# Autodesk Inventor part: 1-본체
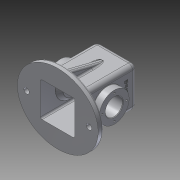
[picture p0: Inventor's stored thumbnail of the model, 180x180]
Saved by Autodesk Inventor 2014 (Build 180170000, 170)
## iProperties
Created: 2017-07
Part Number: 1-본체
Material: Aluminum 6061
Document SubType Name: Modeling
Designer: user
Density: 2.71 g/cm^3
Appearance: Aluminum - Flat
Mass: 892.712 g
Surface Area: 987.354 cm^2
Volume: 329.414 cm^3
Author: user
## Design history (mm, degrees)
sketch "Sketch1" dims "d4" = 65, "d6" = 75
  geometry: 2 further points; 1 other entity
  constraints: 1 coincident, 2 other
extrude "Extrusion1" new body sketch "Sketch1" distance "d7" = 10; taper "d8" = 0 deg
sketch "Sketch2"
  geometry: L1 (-37, -37)-(37, -37); L2 (37, -37)-(37, 37); L3 (37, 37)-(-37, 37); L4 (-37, 37)-(-37, -37); L5 (-37, -37)-(37, 37); L6 (37, -37)-(-37, 37); 1 further point
  constraints: 12 end point, 2 midpoint, 2 parallel, 1 horizontal, 1 perpendicular
  dimensions: "d9" = 74 distance of L3.end L2.end; "d10" = 74 distance of L2.end L1.end
extrude "Extrusion2" join sketch "Sketch2" distance "d11" = 100; taper "d12" = 0 deg
sketch "Sketch3"
  geometry: L1 (-32, 105)-(32, 105); L2 (-32, 105)-(-32, 0); L3 (32, 105)-(32, 0); L4 (-32, 0)-(32, 0); L5 (37, 110)-(-37, 110) reference; 1 further point
  constraints: 8 end point, 3 parallel, 1 perpendicular
  dimensions: "d16" = 5 horizontal distance of L1.end L5.start; "d17" = 110 distance between parallel lines of L4 L5; "d18" = 64 distance between parallel lines of L3 L2; "d19" = 5 distance from line of L5.start L3
extrude "Extrusion3" cut sketch "Sketch3" stored distance "d20" = 64; taper "d21" = 0 deg
sketch "Sketch4"
  geometry: C1 r 27.5 at (37, 45); 1 further point
  constraints: 1 centre point, 1 vertical alignment
  dimensions: "d30" = 55 diameter of C1; "d31" = 55 distance of C1.centre point (37, -10)
extrude "Extrusion4" join sketch "Sketch4" distance "d32" = 13; taper "d33" = 0 deg
sketch "Sketch5"
  geometry: C1 r 27.5 at (37, 45); 1 further point
  constraints: 1 centre point, 1 vertical alignment
  dimensions: "d35" = 55 diameter of C1; "d36" = 55 distance of C1.centre point (37, -10)
extrude "Extrusion5" join sketch "Sketch5" distance "d37" = 13; taper "d38" = 0 deg
sketch "Sketch6"
  geometry: C1 r 27.5 at (0, 0) reference; C2 r 16 at (0, 0); 1 further point
  constraints: 1 centre point, 1 coincident
  dimensions: "d39" = 32 diameter of C2
extrude "Extrusion6" cut sketch "Sketch6" stored distance "d40" = 13; taper "d41" = 0 deg
sketch "Sketch7"
  geometry: L1 (50, 82.5)-(32, 82.5); L2 (32, 82.5)-(25, 75.5); L3 (32, 82.5)-(41.899, 82.5); L4 (25, 75.5)-(25, 55); L5 (25, 55)-(50, 55); L6 (50, 82.5)-(50, 55); 1 further point
  constraints: 12 end point, 2 perpendicular, 1 equal length, 1 horizontal, 1 vertical
  dimensions: "d49" = 135 deg angle of L2 L3; "d50" = 7 horizontal distance of L1.end L2.end; "d51" = 55 vertical distance of point (0, 0) L4.end; "d52" = 90 deg angle of L6 L1; "d55" = 25 horizontal distance of L1.start L2.end
revolve "Revolution1" sketch "Sketch7" stored, may be unused: angle "d54" = 90 deg
sketch "Sketch8"
  geometry: L1 (-50, 82.5)-(-32, 82.5); L2 (-32, 82.5)-(-25, 75.5); L3 (-25, 75.5)-(-25, 55); L4 (-50, 55)-(-25, 55); L5 (-50, 82.5)-(-50, 55); 1 further point
  constraints: 10 end point, 3 perpendicular, 1 vertical
  dimensions: "d63" = 7 horizontal distance of L1.end L2.end; "d64" = 135 deg angle of L2 L1; "d65" = 55 vertical distance of point (0, 0) L3.end; "d66" = 25 distance between parallel lines of L5 L3
revolve "Revolution2" sketch "Sketch8" stored, may be unused: angle "d67" = 90 deg
sketch "Sketch9"
  geometry: C1 r 27.5 at (0, 0) reference; C2 r 16 at (0, 0); 1 further point
  constraints: 1 centre point, 1 coincident
  dimensions: "d68" = 32 diameter of C2
extrude "Extrusion7" cut sketch "Sketch9" stored distance "d69" = 13; taper "d70" = 0 deg
workplane "Work Plane1"
sketch "Sketch10"
  geometry: L1 (20, -20)-(-20, -20); L2 (-20, -20)-(-20, 20); L3 (-20, 20)-(20, 20); L4 (20, 20)-(20, -20); L5 (20, -20)-(-20, 20); L6 (-20, -20)-(20, 20); 1 further point
  constraints: 12 end point, 2 midpoint, 2 parallel, 1 horizontal, 1 perpendicular
  dimensions: "d72" = 40 distance of L2.end L3.end; "d73" = 40 distance of L1.end L2.end
extrude "Extrusion8" join sketch "Sketch10" stored distance "d74" = 13; taper "d75" = 0 deg
sketch "Sketch11"
  geometry: C1 r 14 at (0, 0); 1 further point
  constraints: 1 centre point, 1 coincident
  dimensions: "d76" = 28 diameter of C1
extrude "Extrusion9" cut sketch "Sketch11" distance "d77" = 4; taper "d78" = 0 deg
sketch "Sketch12"
  geometry: C1 r 10.5 at (0, 0); 1 further point
  constraints: 1 centre point, 1 coincident
  dimensions: "d79" = 21 diameter of C1
extrude "Extrusion10" cut sketch "Sketch12" distance "d80" = 50; taper "d81" = 0 deg
feature "FaceDraft1" dims angle "d82" = 5 deg
feature "FaceDraft2" dims angle "d154" = 5 deg
sketch "Sketch13"
  geometry: C1 r 27.5 at (0, 0) reference; 5 further points
  dimensions: "d84" = 59.42432 distance of point (0, -55) point (22.5, 0); "d85" = 77.5 distance of point (0, -55) point (0, 22.5); "d86" = 32.5 distance of point (0, -55) point (0, -22.5); "d87" = 59.42432 distance of point (0, -55) point (-22.5, 0); "d88" = 31.81981 distance of point (22.5, 0) point (0, 22.5); "d89" = 31.81981 distance of point (22.5, 0) point (0, -22.5); "d90" = 45 distance of point (22.5, 0) point (-22.5, 0); "d91" = 22.5 distance of C1.centre point (22.5, 0)
hole "Hole1" sketch "Sketch13" at (0, 22.5), (22.5, 0), (0, -22.5), (-22.5, 0) diameter "d92" = 3.242; stored, may be unused: countersink angle "d96" = 90 deg, drill point angle "d98" = 118 deg; dims "d93" = 8, "d94" = 4, "d95" = 2, "d97" = 10
sketch "Sketch14"
  geometry: C1 r 27.5 at (0, 0) reference; 5 further points
  dimensions: "d100" = 22.5 distance of C1.centre point (22.5, 0); "d101" = 59.42432 distance of point (0, -55) point (22.5, 0); "d102" = 22.5 distance of C1.centre point (0, 22.5); "d103" = 77.5 distance of point (0, -55) point (0, 22.5); "d104" = 22.5 distance of C1.centre point (0, -22.5); "d105" = 22.5 distance of C1.centre point (-22.5, 0); "d106" = 32.5 distance of point (0, -55) point (0, -22.5); "d107" = 59.42432 distance of point (0, -55) point (-22.5, 0)
hole "Hole2" sketch "Sketch14" at (0, 22.5), (-22.5, 0), (0, -22.5), (22.5, 0) diameter "d108" = 3.242; stored, may be unused: countersink angle "d112" = 90 deg, drill point angle "d114" = 118 deg; dims "d109" = 8, "d110" = 4, "d111" = 2, "d113" = 10
sketch "Sketch15"
  geometry: C1 r 5 at (58, 0); C2 r 5 at (-58, 0); 1 further point
  constraints: 2 centre point, 2 horizontal alignment
  dimensions: "d116" = 10 diameter of C1; "d119" = 10 diameter of C2; "d120" = 116 distance of C1.centre C2.centre; "d121" = 58 distance of C1.centre point (0, 0)
extrude "Extrusion11" cut sketch "Sketch15" distance "d122" = 50; taper "d123" = 0 deg
sketch "Sketch17"
  geometry: L1 (82.194, 37)-(10, 55); L2 (82.194, 37)-(10, 37); L3 (10, 37)-(10, 55); 1 further point
  constraints: 6 end point, 1 horizontal, 1 perpendicular
  dimensions: "d133" = 14 deg angle of L1 L2; "d134" = 18 distance of L1.end L2.end; "d135" = 37 distance from line of point (0, 0) L2; "d136" = 55.78548 distance from line of point (0, 0) L1
extrude "Extrusion12" join sketch "Sketch17" stored distance "d137" = 10; taper "d138" = 0 deg
mirror "Mirror1"
chamfer "Chamfer1" distance "d139" = 1; stored, may be unused: second distance "d140" = 2, angle "d141" = 45 deg
chamfer "Chamfer2" distance "d142" = 1; stored, may be unused: second distance "d143" = 2, angle "d144" = 45 deg
fillet "Fillet1" dims "d145" = 8, "d146" = 0.5, "d147" = 3
sketch "Sketch18"
  geometry: L1 (-12.863, 107)-(-9.875, 107) reference; L2 (8, 0)-(8, 89) reference; 2 further points
  constraints: 1 other
  dimensions: "d150" = 30 distance from line of point (-29, 77) L1; "d151" = 37 distance from line of L2 point (-29, 77)
emboss "Emboss1" sketch "Sketch18" dims "d152" = 0.5, "d153" = 0
body "Solid1"
